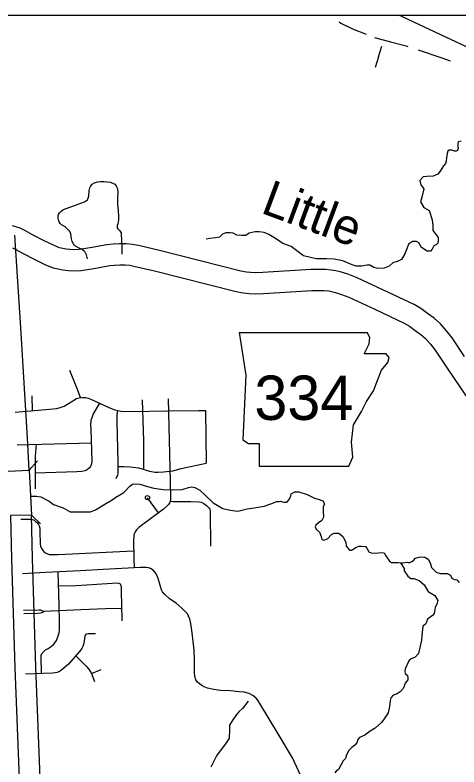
# Model space of a CAD drawing. Extents: x 155 to 3386, y 68 to 2138.
# Drawn here: x 1704.8 to 1855.9, y 1053.4 to 1309 of the extents above; entities that cross this region are included whole.
import ezdxf

# ---------------------------------------------------------------- set-up
doc = ezdxf.new("R2010")
doc.units = 0
for name, color, linetype in [('Default', 7, 'Continuous'), ('E_No Plot', 7, 'Continuous'), ('Level 10', 7, 'Continuous'), ('Level 21', 7, 'Continuous'), ('Level 33', 7, 'Continuous'), ('Level 35', 7, 'Continuous'), ('Level 37', 7, 'Continuous'), ('Level 40', 7, 'Continuous'), ('Level 43', 7, 'Continuous')]:
    doc.layers.add(name, color=color, linetype=linetype)

msp = doc.modelspace()

# ---------------------------------------------------------------- linework, layer by layer
at = {"layer": 'Default'}
msp.add_lwpolyline([(1150.5, 1308.99), (2342.15, 1308.99), (2342.15, 348.58), (1150.5, 348.58)], close=True, dxfattribs=at)
at = {"layer": 'E_No Plot'}
msp.add_lwpolyline([(1150.5, 1308.99), (2342.15, 1308.99), (2342.15, 348.58), (1150.5, 348.58)], close=True, dxfattribs=at)
msp.add_lwpolyline([(1150.5, 1308.99), (2342.15, 1308.99), (2342.15, 348.58), (1150.5, 348.58)], close=True, dxfattribs=at)
at = {"layer": 'Level 10'}
for p, q in [((1702.45, 1153.87), (1709.58, 1154.26)), ((1710.35, 1139.01), (1703.21, 1138.8))]:
    msp.add_line(p, q, dxfattribs=at)
for points in [[(1857.78, 1192.91), (1853.54, 1199.24), (1851.65, 1201.64), (1849.59, 1204.02), (1847.4, 1205.94), (1845.22, 1207.56), (1842.95, 1209.18), (1840.63, 1210.58), (1830.2, 1215.45), (1821.19, 1219.62), (1818.35, 1220.74), (1815.87, 1221.57), (1813.92, 1222.07), (1812.39, 1222.3), (1810.41, 1222.46), (1808.63, 1222.52), (1805.53, 1222.47), (1789.08, 1221.42), (1786.58, 1221.38), (1784.97, 1221.42), (1783.57, 1221.58), (1781.67, 1221.96), (1753.92, 1228.96), (1746.76, 1230.64), (1744.78, 1231.02), (1742.58, 1231.19), (1740.38, 1231.24), (1738.17, 1231.14), (1736, 1230.92), (1730.32, 1229.81), (1726.64, 1229.24), (1724.79, 1229.2), (1723.47, 1229.24), (1722.17, 1229.4), (1721, 1229.64), (1719.94, 1229.89), (1718.06, 1230.66), (1714.71, 1232.24), (1710.73, 1234.32), (1708.38, 1235.62), (1706.49, 1236.56), (1703.9, 1237.29)], [(1709.58, 1154.26), (1708.99, 1165.19), (1706.83, 1200.86), (1704.68, 1234.11)], [(1703.91, 1229.87), (1705.06, 1229.29), (1707.35, 1228.03), (1711.52, 1225.85), (1715.19, 1224.11), (1717.75, 1223.07), (1719.44, 1222.67), (1721.03, 1222.34), (1722.94, 1222.11), (1724.76, 1222.06), (1727.26, 1222.11), (1731.55, 1222.77), (1737.04, 1223.85), (1738.69, 1224.01), (1740.46, 1224.09), (1742.23, 1224.05), (1743.83, 1223.93), (1745.26, 1223.65), (1752.22, 1222.02), (1780.1, 1214.99), (1782.47, 1214.51), (1784.48, 1214.29), (1786.56, 1214.24), (1789.37, 1214.29), (1805.81, 1215.33), (1808.58, 1215.37), (1810.02, 1215.33), (1811.55, 1215.21), (1812.48, 1215.06), (1813.85, 1214.71), (1815.92, 1214.02), (1818.38, 1213.05), (1827.19, 1208.97), (1837.26, 1204.27), (1839.02, 1203.21), (1841.01, 1201.79), (1842.91, 1200.38), (1844.51, 1198.97), (1846.14, 1197.09), (1847.76, 1195.04), (1851.86, 1188.92), (1860.88, 1175.59)], [(1709.58, 1154.26), (1710.28, 1141.27), (1710.35, 1139.01)], [(1703.21, 1138.8), (1703.63, 1124.16), (1704.7, 1087.09), (1706.16, 1049.3), (1707.07, 1031.59), (1707.55, 1017.2), (1707.49, 1000.4)], [(1714.63, 1000.37), (1714.7, 1017.31), (1714.21, 1031.89), (1713.29, 1049.62), (1711.84, 1087.34), (1710.77, 1124.37), (1710.35, 1139.01)]]:
    msp.add_lwpolyline(points, dxfattribs=at)
at = {"layer": 'Level 21'}
for p, q in [((1781.12, 1201.04), (1783.29, 1186.54)), ((1825.59, 1199.34), (1824.59, 1201.02)), ((1825.35, 1197.17), (1825.59, 1199.34)), ((1823.66, 1193.79), (1825.35, 1197.17)), ((1831.15, 1193.79), (1823.66, 1193.79)), ((1832.11, 1192.58), (1831.15, 1193.79)), ((1831.63, 1190.89), (1832.11, 1192.58)), ((1829.46, 1188.23), (1831.63, 1190.89)), ((1783.29, 1186.54), (1782.33, 1164.54)), ((1828.25, 1185.09), (1829.46, 1188.23)), ((1826.8, 1181.22), (1828.25, 1185.09)), ((1824.38, 1177.59), (1826.8, 1181.22)), ((1822.69, 1174.21), (1824.38, 1177.59)), ((1820.03, 1169.62), (1822.69, 1174.21)), ((1819.3, 1163.82), (1820.03, 1169.62)), ((1782.33, 1164.54), (1784.26, 1163.33)), ((1784.26, 1163.33), (1787.89, 1163.33)), ((1787.89, 1163.33), (1787.89, 1155.6)), ((1819.79, 1158.74), (1819.3, 1163.82)), ((1818.34, 1155.6), (1819.79, 1158.74)), ((1787.89, 1155.6), (1818.34, 1155.6))]:
    msp.add_line(p, q, dxfattribs=at)
msp.add_lwpolyline([(1781.12, 1201.04), (1824.59, 1201.02)], dxfattribs=at)
at = {"layer": 'Level 33'}
for points in [[(1835.49, 1308.99), (1836.53, 1308.49), (1851.31, 1301.59), (1858.12, 1298.41), (1866.53, 1295.37), (1876.36, 1292.56), (1885.03, 1290.02), (1891.48, 1288.41), (1894, 1287.38), (1895.33, 1286.16), (1896.25, 1284.9), (1896.84, 1283.22), (1896.9, 1282.78), (1897.81, 1277.07)], [(1729.43, 1226.06), (1729.09, 1227.42), (1728.69, 1228.33), (1728.26, 1228.73), (1727.38, 1229.35), (1726.63, 1229.73), (1725.38, 1230.37), (1725.04, 1230.73), (1724.66, 1231.21), (1724.24, 1231.95), (1724.04, 1232.87), (1723.75, 1234.65), (1723.38, 1235.44), (1722.69, 1236.16), (1721.82, 1236.96), (1720.63, 1237.7), (1720.16, 1238.12), (1719.83, 1238.7), (1719.63, 1239.38), (1719.51, 1240.06), (1719.48, 1240.8), (1719.6, 1241.18), (1719.92, 1241.72), (1720.35, 1242.25), (1721.08, 1242.76), (1721.86, 1243.08), (1724.09, 1243.91), (1727.21, 1244.99), (1728.48, 1245.48), (1729.42, 1246.14), (1729.71, 1246.72), (1729.87, 1247.48), (1730.05, 1249.35), (1730.23, 1250.26), (1730.53, 1250.93), (1731.09, 1251.53), (1731.84, 1251.96), (1732.83, 1252.27), (1733.85, 1252.37), (1735.15, 1252.4), (1736.09, 1252.33), (1737.17, 1252.15), (1738.06, 1251.88), (1738.7, 1251.45), (1739.2, 1250.92), (1739.56, 1250.21), (1739.71, 1249.69), (1739.75, 1248.83), (1739.65, 1246.72), (1739.69, 1244.55), (1739.87, 1242.55), (1740.03, 1240.49), (1740, 1239.34), (1739.92, 1238.74), (1739.75, 1237.99), (1739.56, 1237.41), (1739.52, 1237), (1739.59, 1236.64), (1739.81, 1236.33), (1740.36, 1235.76), (1740.68, 1235.33), (1740.86, 1234.92), (1740.94, 1234.28), (1741.02, 1232.69), (1741.1, 1229.37), (1741.11, 1227.65)], [(1727.03, 1178.93), (1725.77, 1182.25), (1723.46, 1188.12)], [(1704.88, 1173.96), (1716.56, 1174.95), (1718.97, 1175.21), (1720.15, 1175.52), (1721.49, 1176.06), (1724.44, 1177.89), (1725.66, 1178.58), (1726.62, 1178.89), (1727.69, 1179), (1728.8, 1178.93), (1729.72, 1178.7), (1730.82, 1178.24), (1736.45, 1175.71), (1737.86, 1175.06), (1738.7, 1174.79), (1740.86, 1174.33), (1744.34, 1174.22), (1756.65, 1174.45), (1767.25, 1174.56), (1769.57, 1174.58)], [(1710.75, 1174.46), (1710.67, 1179.57)], [(1756.95, 1178.51), (1757.51, 1155.08), (1757.73, 1145.34), (1757.66, 1144.1), (1757.43, 1143.31), (1756.98, 1142.56), (1756.49, 1141.99), (1755.29, 1140.98), (1746.95, 1134.81), (1746.12, 1134.02), (1745.63, 1133.34), (1745.29, 1132.67), (1745.18, 1131.8), (1745.07, 1130.33), (1745.26, 1124.32), (1745.31, 1121.05)], [(1733.53, 1177.02), (1731.38, 1173.39), (1730.94, 1172.08), (1730.63, 1171.14), (1730.51, 1169.71), (1730.57, 1168.15), (1730.88, 1157.35), (1730.8, 1156.37), (1730.52, 1155.56), (1730.12, 1155.09), (1729.37, 1154.4), (1728.56, 1153.99), (1727.56, 1153.81), (1725.84, 1153.68), (1711.65, 1153.24)], [(1748.04, 1178.17), (1748.45, 1164.26), (1748.53, 1154.51)], [(1739.62, 1174.6), (1739.44, 1173.12), (1739.38, 1170.66), (1739.72, 1157.02), (1739.82, 1153.95), (1739.75, 1153.14), (1739.63, 1152.45), (1739.26, 1151.64), (1739.07, 1151.33)], [(1769.57, 1174.58), (1769.88, 1156.68)], [(1705.53, 1162.93), (1730.7, 1163.54)], [(1711.93, 1163.08), (1711.68, 1159.05), (1711.62, 1147.88)], [(1739.77, 1155.5), (1741.94, 1155.5), (1744.01, 1155.38), (1746.75, 1155.01), (1750.55, 1153.95), (1752.5, 1153.62), (1753.55, 1153.58), (1755.32, 1153.65), (1758.51, 1154.03), (1761.37, 1154.78), (1769.88, 1156.68)], [(1753.65, 1139.76), (1749.85, 1144.91)], [(1757.56, 1143.74), (1758.52, 1143.6), (1764.66, 1143.57), (1767.42, 1143.54), (1768.16, 1143.4), (1769.06, 1142.97), (1769.93, 1142.3), (1770.73, 1141.5), (1771.06, 1141), (1771.19, 1140.6), (1771.23, 1139.93), (1771.33, 1128.42)], [(1706.81, 1137.57), (1709.94, 1137.57), (1710.65, 1137.48), (1711.31, 1137.23), (1711.8, 1136.83), (1712.44, 1136.31), (1712.78, 1135.79), (1713.03, 1135.29), (1713.19, 1134.5), (1713.25, 1133.17), (1713.36, 1129.32), (1713.5, 1128.36), (1713.86, 1127.57), (1714.27, 1126.93), (1714.81, 1126.32), (1715.56, 1125.89), (1716.42, 1125.62), (1717.12, 1125.56), (1719.5, 1125.59), (1724.27, 1125.79), (1728.83, 1126.03), (1738.04, 1126.49), (1745.18, 1126.85)], [(1803.82, 1046.34), (1799.27, 1056.43), (1794.37, 1064.63), (1788.13, 1074.99), (1787.38, 1076.03), (1786.71, 1076.82), (1785.67, 1077.65), (1784.46, 1078.29), (1782.75, 1078.77), (1781.07, 1078.95), (1778.12, 1079.2), (1774.71, 1079.39), (1772.46, 1079.7), (1770.28, 1080.18), (1769.2, 1080.6), (1768.32, 1081.06), (1767.6, 1081.62), (1766.91, 1082.24), (1766.35, 1083.01), (1765.97, 1084.13), (1765.83, 1085.51), (1765.87, 1089.9), (1765.79, 1093.1), (1765.12, 1098.93), (1764.62, 1102.18), (1764.27, 1103.59), (1763.83, 1104.65), (1763.44, 1105.38), (1762.79, 1106.07), (1761.54, 1107.32), (1759.57, 1109.04), (1757.36, 1110.56), (1755.64, 1112.12), (1754.93, 1112.93), (1754.58, 1113.6), (1754.27, 1114.68), (1753.48, 1117.43), (1753.21, 1118.34), (1752.62, 1119.34), (1751.77, 1120.32), (1750.92, 1120.82), (1750.23, 1121.05), (1749.38, 1121.15), (1747.43, 1121.17), (1734.82, 1120.44), (1726.98, 1120.01), (1715.1, 1119.45), (1707.35, 1119.05)], [(1713.82, 1085.12), (1713.69, 1090.97), (1713.73, 1091.37), (1713.9, 1091.76), (1714.17, 1092.12), (1714.55, 1092.61), (1715.2, 1093.15), (1716.06, 1093.6), (1717.03, 1094.28), (1717.98, 1095.12), (1718.88, 1096.34), (1719.38, 1097.56), (1719.84, 1098.93), (1719.95, 1099.83), (1719.95, 1102.51), (1719.81, 1108.5), (1719.42, 1119.65)], [(1719.58, 1114.9), (1725.54, 1115.11), (1732.68, 1115.55), (1737.89, 1115.87), (1739.54, 1115.94), (1740.1, 1115.9), (1740.55, 1115.66), (1740.73, 1115.39), (1740.84, 1115), (1740.88, 1114.51), (1740.91, 1112.77), (1741.06, 1108.64), (1741.18, 1103)], [(1741.09, 1107.2), (1735.6, 1107.16), (1727.2, 1106.82), (1714.63, 1106.21)], [(1707.71, 1106.68), (1713.03, 1106.77), (1713.46, 1106.73), (1713.93, 1106.59), (1714.36, 1106.35), (1714.63, 1106.21), (1714.32, 1105.96), (1713.87, 1105.74), (1713.37, 1105.63), (1712.53, 1105.56), (1707.75, 1105.38)], [(1732.18, 1098.61), (1729.68, 1098.61), (1729.09, 1098.52), (1728.75, 1098.3), (1728.6, 1098.09), (1728.51, 1097.73), (1728.42, 1097.14), (1728.32, 1096.13), (1728.03, 1094.95), (1727.85, 1094.37), (1727.53, 1093.65), (1726.72, 1092.61), (1722.97, 1088.36), (1721.55, 1087.05), (1720.62, 1086.29), (1719.92, 1085.84), (1719.14, 1085.52), (1718.43, 1085.32), (1717.51, 1085.23), (1708.36, 1084.95)], [(1725.42, 1091.14), (1727.97, 1088.67), (1729.12, 1087.52), (1729.8, 1086.69), (1730.7, 1085.37), (1731.88, 1082.42)], [(1730.79, 1085.12), (1734.14, 1086.51)]]:
    msp.add_lwpolyline(points, dxfattribs=at)
msp.add_circle((1749.85, 1144.91), 0.714, dxfattribs=at)
at = {"layer": 'Level 35'}
for points in [[(1856.66, 1266.1), (1855.61, 1265.85), (1855.45, 1265.18), (1855.52, 1264.32), (1855.55, 1263.75), (1855.39, 1262.89), (1854.88, 1262.74), (1854.31, 1262.74), (1853.45, 1263.08)], [(1853.45, 1263.08), (1852.5, 1263.08), (1852.08, 1262.73), (1851.81, 1261.94), (1851.6, 1260.4), (1851.57, 1259.27), (1851.29, 1258.51), (1850.61, 1257.71)], [(1850.61, 1257.71), (1849.53, 1255.87), (1848.71, 1254.85), (1847.12, 1254.22), (1844.96, 1254.09), (1843.69, 1254.03), (1842.55, 1252.76), (1842.87, 1251.23), (1843.88, 1249.96), (1843.18, 1247.04), (1842.8, 1245.52), (1843.88, 1243.61), (1845.72, 1242.53), (1846.8, 1239.42), (1846.99, 1237.45), (1846.99, 1235.73), (1847.82, 1234.72), (1848.77, 1233.32), (1848.77, 1232.49), (1848.64, 1231.48), (1848.2, 1230.97), (1847.31, 1230.52), (1846.8, 1229.44), (1846.17, 1228.75), (1845.02, 1228.75), (1843.12, 1230.02), (1842.17, 1231.54), (1841.41, 1231.99), (1840.01, 1231.99), (1838.68, 1231.1), (1838.17, 1229.51), (1837.28, 1227.54), (1836.26, 1225.89), (1834.87, 1225.25), (1833.41, 1224.74), (1832.14, 1223.6), (1830.42, 1222.96), (1828.26, 1222.77), (1826.87, 1223.16), (1825.53, 1223.92), (1824.64, 1223.92), (1822.68, 1223.6), (1822.23, 1223.6), (1820.9, 1223.6), (1819.56, 1224.11), (1816.33, 1225.44), (1813.41, 1225.95), (1810.74, 1226.08), (1807.31, 1226.08), (1802.93, 1227.16), (1802.1, 1227.79), (1798.74, 1230.27), (1795.88, 1231.29), (1793.41, 1233.07), (1791.18, 1234.34), (1789.6, 1235.1), (1787.82, 1235.29), (1786.49, 1235.29), (1784.45, 1234.78), (1783.31, 1234.02), (1781.85, 1234.02), (1780.26, 1234.21), (1779.06, 1234.84), (1777.98, 1234.97), (1776.52, 1234.91), (1775.44, 1234.46), (1774.36, 1233.45), (1773.03, 1233.26), (1771.12, 1233.07), (1769.85, 1232.75)], [(1710.41, 1145.48), (1711.05, 1145.44), (1712.06, 1145.44), (1713.53, 1145.24), (1716.35, 1143.76), (1717.9, 1142.62), (1721.18, 1141.41), (1723.6, 1140.14), (1727.49, 1140.14), (1730.51, 1140.14), (1732.12, 1140.74), (1735.34, 1142.75), (1737.89, 1144.23), (1739.09, 1145.1), (1741.78, 1146.71), (1743.86, 1148.79), (1744.73, 1149.47), (1745.33, 1149.6), (1747.21, 1149.53), (1749.89, 1148.73), (1751.97, 1148.19), (1755.19, 1147.72), (1758.48, 1147.59), (1761.7, 1147.72), (1763.85, 1148.33), (1764.79, 1148.59), (1765.93, 1148.33), (1767.67, 1147.45), (1769.55, 1145.77), (1772.23, 1143.16), (1775.52, 1141.21), (1778, 1140.61), (1780.62, 1140.34), (1783.84, 1141.08), (1786.19, 1141.48), (1789.54, 1142.02), (1791.82, 1142.82), (1793.9, 1143.63), (1794.64, 1143.63)], [(1793.9, 1143.63), (1794.98, 1143.69), (1796.32, 1143.36), (1797.19, 1143.43), (1797.66, 1143.76), (1798.33, 1144.63), (1798.6, 1145.57), (1798.8, 1146.18), (1800.01, 1146.85), (1801.42, 1146.85), (1804.17, 1145.98), (1806.65, 1144.7), (1807.92, 1144.37), (1809.53, 1143.83), (1810.07, 1142.82), (1809.6, 1141.75), (1809.67, 1140.41), (1809.73, 1138.26), (1809.2, 1137.18), (1808.12, 1136.31), (1807.12, 1135.57), (1806.98, 1134.97), (1807.32, 1134.23), (1808.39, 1133.22), (1809, 1131.75), (1809.2, 1130.74), (1809.87, 1130.47), (1811.08, 1130.87), (1812.48, 1132.35), (1813.36, 1132.89), (1814.3, 1132.89), (1814.97, 1132.89), (1816.38, 1131.75), (1817.38, 1129.8), (1817.45, 1128.46), (1818.59, 1127.12), (1819.26, 1127.05), (1819.86, 1127.45), (1820.8, 1127.99), (1821.74, 1128.46), (1822.61, 1128.46), (1824.02, 1128.26), (1824.49, 1127.72), (1825.23, 1126.51), (1825.97, 1126.18), (1827.78, 1126.04), (1829.26, 1126.31), (1830.4, 1126.11), (1830.93, 1125.1), (1832.27, 1123.29), (1832.95, 1122.89), (1833.82, 1122.89), (1835.16, 1122.89), (1835.83, 1122.75), (1836.17, 1122.42), (1837.17, 1120.87), (1837.17, 1120), (1838.51, 1118.19), (1839.52, 1117.45), (1840.53, 1117.38), (1842.34, 1116.71), (1844.01, 1115.24), (1845.42, 1113.02), (1847.7, 1111.68), (1848.64, 1110), (1848.51, 1109.06), (1847.77, 1107.58), (1847.44, 1105.57), (1846.83, 1104.83), (1845.22, 1103.56), (1844.82, 1102.55), (1844.48, 1101.95), (1843.61, 1101.21), (1843.41, 1100), (1843.21, 1098.26), (1843.14, 1096.51), (1842.67, 1094.43), (1842.07, 1091.88), (1840.93, 1090.67), (1839.65, 1090.07), (1838.85, 1089.4), (1837.57, 1086.78), (1837.44, 1085.77), (1837.51, 1085.17), (1838.31, 1084.5), (1838.51, 1083.62), (1838.51, 1082.95), (1837.57, 1081.88), (1837.17, 1080.8), (1836.84, 1080), (1835.83, 1078.93), (1834.82, 1078.25), (1833.48, 1077.72), (1832.68, 1076.91), (1832.41, 1075.97), (1832.21, 1073.89), (1831.8, 1071.81), (1831.13, 1070.8), (1830.46, 1069.73), (1829.52, 1068.45), (1827.38, 1066.58)], [(1835.83, 1122.75), (1836.93, 1122.72), (1837.9, 1122.96), (1838.63, 1122.9), (1839.17, 1122.84), (1839.84, 1123.21), (1840.39, 1123.57), (1841.11, 1124.36), (1842.69, 1124.85), (1844.21, 1124.66), (1845.42, 1124.06), (1846.09, 1122.78), (1846.58, 1121.2), (1848.1, 1119.62), (1849.55, 1119.14), (1850.71, 1119.14), (1851.86, 1119.08), (1853.01, 1118.59), (1853.44, 1117.56), (1854.23, 1117.13), (1855.14, 1117.01), (1855.99, 1116.1)], [(1784.18, 1075.76), (1782.2, 1073.27), (1780.98, 1072.15), (1780.16, 1071.24), (1778.74, 1069.1), (1777.73, 1067.58), (1777.83, 1066.05), (1777.62, 1063.2), (1776.71, 1061.68), (1775.59, 1060.15), (1773.35, 1057.2), (1771.42, 1053.24)], [(1827.38, 1066.58), (1825.7, 1065.57), (1823.89, 1064.16), (1822.01, 1063.42), (1821.41, 1062.68), (1821.07, 1061.54), (1820.4, 1060.74), (1819.39, 1060), (1818.39, 1058.92), (1817.65, 1057.45), (1817.31, 1056.24), (1816.44, 1055.43), (1815.7, 1054.02), (1814.9, 1052.48), (1814.03, 1051.88), (1813.57, 1051.35)]]:
    msp.add_lwpolyline(points, dxfattribs=at)
at = {"layer": 'Level 37'}
for points in [[(1712.44, 1157.45), (1709.58, 1154.26)], [(1710.35, 1139.01), (1713.46, 1136.07)]]:
    msp.add_lwpolyline(points, dxfattribs=at)
at = {"layer": 'Level 40'}
for q in [(1829.61, 1298.37), (1827.38, 1291.16)]:
    msp.add_line((1828.5, 1294.76), q, dxfattribs=at)
at = {"layer": 'Level 43'}
for points in [[(1815.11, 1306.67), (1815.68, 1306.27), (1819.6, 1304.3), (1824.25, 1302.45)], [(1827.15, 1301.3), (1832.58, 1299.91), (1837.9, 1298.51), (1838.42, 1298.34)], [(1842.01, 1297.16), (1850.08, 1294.49), (1852.89, 1293.46)]]:
    msp.add_lwpolyline(points, dxfattribs=at)

# ---------------------------------------------------------------- texts
at = {"layer": 'Level 21'}
msp.add_text('334', height=15.086, dxfattribs=at).set_placement((1786.24, 1171.34))
at = {"layer": 'Level 43'}
msp.add_text('Little', height=12.069, rotation=339.562, dxfattribs=at).set_placement((1788.04, 1241.88))

doc.saveas('drawing.dxf')
